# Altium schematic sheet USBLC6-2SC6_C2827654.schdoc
size 127 x 101 mm
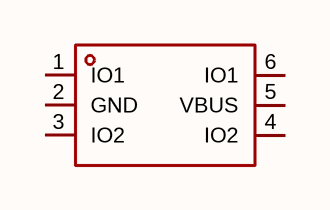
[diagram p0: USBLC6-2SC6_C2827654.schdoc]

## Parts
D?  usblc6-2sc6_c2827654  [SOT-23-6_L2.9-W1.6-P0.95-LS2.8-BL]  (value not drawn)

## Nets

Not connected (* = marked no-connect by the designer): D? 1(IO1) 2(GND) 3(IO2) 4(IO2) 5(VBUS) 6(IO1)

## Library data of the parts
D? = usblc6-2sc6_c2827654: 极性:单向;反向截止电压(Vrwm):5V;钳位电压:12V;峰值脉冲电流(Ipp):6A;峰值脉冲功率(Ppp):150W;击穿电压:6V;; Manufacturer: TECH PUBLIC(台舟); AddInBom: yes; ModelId: 18da8f6c14a34920b3e136b5c401a119; ModelName: SOT-23-6_L2.9-W1.6-H1.5-LS2.8-P0.95; ModelTransform: 110.236,113.364,0,90,0,0,0.0005,0.0005,0; Polarity: 单向; Reverse Stand-Off Voltage (Vrwm): 5V; Clamping Voltage: 12V; Peak Pulse Current (Ipp): 6A; Peak Pulse Power Dissipation (Ppp): 150W; Voltage - Breakdown: 6V; Reverse Leakage Current (Ir): 80nA; Number of Channels: 双路; level of protection: IEC 61000-4-2；IEC 61000-4-4；IEC 61000-4-5; Type: ESD; Junction Capacitance: 0.35pF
